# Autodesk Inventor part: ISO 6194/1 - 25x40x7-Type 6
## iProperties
IsCustomPart: 0
Created: 2007-11
Part Number: ISO 6194/1 - 25x40x7-Type 6
Material: Rubber
Description: Rotary shaft lip type seals 6 - Assembled with minor lip
Document SubType Name: Modeling
Standard: ISO 6194/1
Designer: CM
Standards Organization: ISO
Language: en-US
Size Designation: 25x40x7-Type 6
Categories: <MemberInstance><Categories><Category DisplayName="Shaft Parts" InternalName="7f7aeb1f-a693-4053-b835-cee3144e0d98" Mnemonic="SHFT"><Category DisplayName="Seali
Density: 0.93 g/cm^3
Mass: 1.80295 g
Surface Area: 51.0286 cm^2
Volume: 1.93866 cm^3
Author: CM
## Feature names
1. Revolution1
2. Fillet1
3. Fillet2
